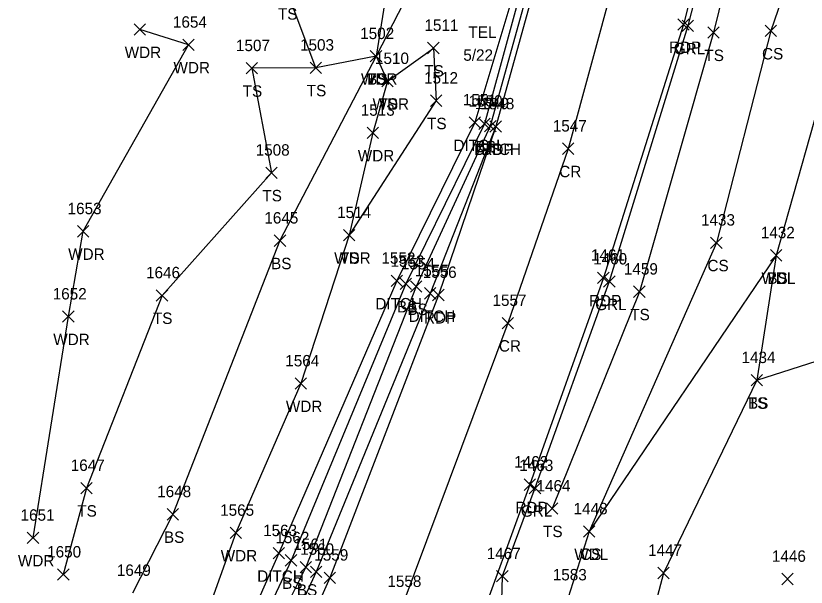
# Model space of a CAD drawing. Extents: x 1551995 to 1555700, y 777276 to 783130.
# Drawn here: x 1554731.9 to 1554870.3, y 777546.8 to 777646.9 of the extents above; entities that cross this region are included whole.
import ezdxf

# ---------------------------------------------------------------- set-up
doc = ezdxf.new("R2010")
doc.units = 0
for name, color, linetype in [('D_A', 7, 'Continuous'), ('D_I', 7, 'Continuous'), ('D_TIC', 7, 'Continuous'), ('DD', 7, 'Continuous'), ('L_A', 7, 'Continuous'), ('L_I', 7, 'Continuous'), ('L_TIC', 7, 'Continuous'), ('LAWA', 7, 'Continuous'), ('LELB', 7, 'Continuous'), ('P_A', 7, 'Continuous'), ('P_I', 7, 'Continuous'), ('P_TIC', 7, 'Continuous'), ('PET', 7, 'Continuous'), ('PRC', 7, 'Continuous'), ('R_A', 7, 'Continuous'), ('R_I', 7, 'Continuous'), ('R_TIC', 7, 'Continuous'), ('RGR', 7, 'Continuous'), ('U_A', 7, 'Continuous'), ('U_C', 7, 'Continuous')]:
    doc.layers.add(name, color=color, linetype=linetype)

msp = doc.modelspace()

# ---------------------------------------------------------------- linework, layer by layer
at = {"layer": 'D_TIC'}
for points in [[(1554811.27, 777627.19), (1554813.27, 777629.19)], [(1554813.27, 777627.19), (1554811.27, 777629.19)], [(1554814.91, 777626.5), (1554816.91, 777628.5)], [(1554816.91, 777626.5), (1554814.91, 777628.5)], [(1554797.58, 777599.46), (1554799.58, 777601.46)], [(1554799.58, 777599.46), (1554797.58, 777601.46)], [(1554803.43, 777597.27), (1554805.43, 777599.27)], [(1554805.43, 777597.27), (1554803.43, 777599.27)], [(1554776.91, 777551.75), (1554778.91, 777553.75)], [(1554778.91, 777551.75), (1554776.91, 777553.75)], [(1554783.48, 777548.49), (1554785.48, 777550.49)], [(1554785.48, 777548.49), (1554783.48, 777550.49)]]:
    msp.add_lwpolyline(points, dxfattribs=at)
at = {"layer": 'DD'}
for points in [[(1554853.39, 777826.98), (1554841.81, 777777.5), (1554835.76, 777743.69), (1554828.13, 777697.14), (1554822.33, 777678.76), (1554820.5, 777673.08), (1554821.28, 777667.69), (1554820.54, 777665.87), (1554819.99, 777658.61), (1554821.52, 777659.17), (1554812.27, 777628.19), (1554798.58, 777600.46), (1554777.91, 777552.75), (1554765.73, 777525.09), (1554749.72, 777489.17), (1554733.83, 777456.87), (1554735, 777456.04), (1554736.9, 777455.11), (1554739.85, 777453.59)], [(1554815.91, 777627.5), (1554804.43, 777598.27), (1554784.48, 777549.49), (1554771.86, 777522.02), (1554755.84, 777486.17), (1554739.85, 777453.59)]]:
    msp.add_lwpolyline(points, dxfattribs=at)
at = {"layer": 'L_TIC'}
for points in [[(1554752.57, 777643.48), (1554754.57, 777645.48)], [(1554754.57, 777643.48), (1554752.57, 777645.48)], [(1554853.06, 777642.96), (1554855.06, 777644.96)], [(1554855.06, 777642.96), (1554853.06, 777644.96)], [(1554863.12, 777643.24), (1554865.12, 777645.24)], [(1554865.12, 777643.24), (1554863.12, 777645.24)], [(1554761.12, 777640.8), (1554763.12, 777642.8)], [(1554763.12, 777640.8), (1554761.12, 777642.8)], [(1554803.99, 777640.24), (1554805.99, 777642.24)], [(1554805.99, 777640.24), (1554803.99, 777642.24)], [(1554793.95, 777638.81), (1554795.95, 777640.81)], [(1554795.95, 777638.81), (1554793.95, 777640.81)], [(1554793.95, 777638.81), (1554795.95, 777640.81)], [(1554795.95, 777638.81), (1554793.95, 777640.81)], [(1554793.95, 777638.81), (1554795.95, 777640.81)], [(1554795.95, 777638.81), (1554793.95, 777640.81)], [(1554783.41, 777636.79), (1554785.41, 777638.79)], [(1554785.41, 777636.79), (1554783.41, 777638.79)], [(1554783.41, 777636.79), (1554785.41, 777638.79)], [(1554785.41, 777636.79), (1554783.41, 777638.79)], [(1554772.19, 777636.7), (1554774.19, 777638.7)], [(1554774.19, 777636.7), (1554772.19, 777638.7)], [(1554795.98, 777634.44), (1554797.98, 777636.44)], [(1554797.98, 777634.44), (1554795.98, 777636.44)], [(1554795.98, 777634.44), (1554797.98, 777636.44)], [(1554797.98, 777634.44), (1554795.98, 777636.44)], [(1554804.49, 777631.02), (1554806.49, 777633.02)], [(1554806.49, 777631.02), (1554804.49, 777633.02)], [(1554812.94, 777626.98), (1554814.94, 777628.98)], [(1554814.94, 777626.98), (1554812.94, 777628.98)], [(1554813.97, 777626.54), (1554815.97, 777628.54)], [(1554815.97, 777626.54), (1554813.97, 777628.54)], [(1554793.4, 777625.38), (1554795.4, 777627.38)], [(1554795.4, 777625.38), (1554793.4, 777627.38)], [(1554775.64, 777618.39), (1554777.64, 777620.39)], [(1554777.64, 777618.39), (1554775.64, 777620.39)], [(1554742.67, 777608.14), (1554744.67, 777610.14)], [(1554744.67, 777608.14), (1554742.67, 777610.14)], [(1554777.13, 777606.5), (1554779.13, 777608.5)], [(1554779.13, 777606.5), (1554777.13, 777608.5)], [(1554789.25, 777607.46), (1554791.25, 777609.46)], [(1554791.25, 777607.46), (1554789.25, 777609.46)], [(1554789.25, 777607.46), (1554791.25, 777609.46)], [(1554791.25, 777607.46), (1554789.25, 777609.46)], [(1554853.56, 777606.14), (1554855.56, 777608.14)], [(1554855.56, 777606.14), (1554853.56, 777608.14)], [(1554864.05, 777603.93), (1554866.05, 777605.93)], [(1554866.05, 777603.93), (1554864.05, 777605.93)], [(1554864.05, 777603.93), (1554866.05, 777605.93)], [(1554866.05, 777603.93), (1554864.05, 777605.93)], [(1554799.18, 777598.92), (1554801.18, 777600.92)], [(1554801.18, 777598.92), (1554799.18, 777600.92)], [(1554800.99, 777598.47), (1554802.99, 777600.47)], [(1554802.99, 777598.47), (1554800.99, 777600.47)], [(1554756.47, 777596.91), (1554758.47, 777598.91)], [(1554758.47, 777596.91), (1554756.47, 777598.91)], [(1554840.07, 777597.56), (1554842.07, 777599.56)], [(1554842.07, 777597.56), (1554840.07, 777599.56)], [(1554740.06, 777593.2), (1554742.06, 777595.2)], [(1554742.06, 777593.2), (1554740.06, 777595.2)], [(1554780.8, 777581.48), (1554782.8, 777583.48)], [(1554782.8, 777581.48), (1554780.8, 777583.48)], [(1554860.66, 777582.06), (1554862.66, 777584.06)], [(1554862.66, 777582.06), (1554860.66, 777584.06)], [(1554860.66, 777582.06), (1554862.66, 777584.06)], [(1554862.66, 777582.06), (1554860.66, 777584.06)], [(1554743.22, 777563.17), (1554745.22, 777565.17)], [(1554745.22, 777563.17), (1554743.22, 777565.17)], [(1554824.8, 777559.58), (1554826.8, 777561.58)], [(1554826.8, 777559.58), (1554824.8, 777561.58)], [(1554758.36, 777558.57), (1554760.36, 777560.57)], [(1554760.36, 777558.57), (1554758.36, 777560.57)], [(1554769.39, 777555.32), (1554771.39, 777557.32)], [(1554771.39, 777555.32), (1554769.39, 777557.32)], [(1554831.26, 777555.58), (1554833.26, 777557.58)], [(1554833.26, 777555.58), (1554831.26, 777557.58)], [(1554831.26, 777555.58), (1554833.26, 777557.58)], [(1554833.26, 777555.58), (1554831.26, 777557.58)], [(1554733.87, 777554.45), (1554735.87, 777556.45)], [(1554735.87, 777554.45), (1554733.87, 777556.45)], [(1554779.06, 777550.51), (1554781.06, 777552.51)], [(1554781.06, 777550.51), (1554779.06, 777552.51)], [(1554781.65, 777549.32), (1554783.65, 777551.32)], [(1554783.65, 777549.32), (1554781.65, 777551.32)], [(1554844.3, 777548.29), (1554846.3, 777550.29)], [(1554846.3, 777548.29), (1554844.3, 777550.29)], [(1554739.18, 777548.01), (1554741.18, 777550.01)], [(1554741.18, 777548.01), (1554739.18, 777550.01)], [(1554866.04, 777547.25), (1554868.04, 777549.25)], [(1554868.04, 777547.25), (1554866.04, 777549.25)]]:
    msp.add_lwpolyline(points, dxfattribs=at)
at = {"layer": 'LAWA'}
for points in [[(1554924.17, 777845.95), (1554911.99, 777797.39), (1554901.73, 777752.36), (1554891.43, 777715.92), (1554886.53, 777681.63), (1554885.54, 777676.35), (1554886.43, 777672.72), (1554885.1, 777668.28), (1554876.24, 777640.92), (1554874.65, 777639.02), (1554865.05, 777604.93), (1554832.26, 777556.58), (1554828.6, 777545), (1554825.77, 777534.55), (1554825.26, 777531.03), (1554824.11, 777527.47), (1554817.13, 777514.36), (1554810.78, 777500.84), (1554797.7, 777469.38), (1554813.54, 777462.7)], [(1554848.67, 777827.4), (1554836.72, 777779.63), (1554829.79, 777744.11), (1554825.78, 777741.3), (1554822.18, 777720.94), (1554819.26, 777705.66), (1554810.77, 777674.16), (1554804.68, 777658.7), (1554794.95, 777639.81), (1554796.98, 777635.44), (1554794.4, 777626.38), (1554790.25, 777608.46), (1554781.8, 777582.48), (1554770.39, 777556.32), (1554759.95, 777527.2), (1554742.53, 777489.58), (1554728.19, 777462.54)], [(1554734.87, 777555.45), (1554741.06, 777594.2), (1554743.67, 777609.14), (1554762.12, 777641.8), (1554753.57, 777644.48)]]:
    msp.add_lwpolyline(points, dxfattribs=at)
at = {"layer": 'LELB'}
for points in [[(1554956.78, 778082.85), (1554952.54, 778067.25), (1554941.7, 778025.45), (1554932.23, 777987.42), (1554924.92, 777953.42), (1554914.28, 777909.64), (1554906.04, 777867.54), (1554895.88, 777821.34), (1554882.23, 777767.05), (1554874.85, 777730.37), (1554865.16, 777689.06), (1554854.06, 777643.96), (1554841.07, 777598.56), (1554825.8, 777560.58)], [(1554954.84, 778026.93), (1554940.94, 777981.64), (1554932.87, 777954.14), (1554929.76, 777924.84), (1554918.75, 777893.91), (1554912.39, 777848.48), (1554900.26, 777799.7), (1554891.71, 777757.62), (1554881.43, 777720.27), (1554874.58, 777680.06), (1554873.83, 777672.65), (1554864.12, 777644.24), (1554854.56, 777607.14), (1554832.26, 777556.58)], [(1554818.74, 777989.99), (1554826.95, 777965.67), (1554828.21, 777938.79), (1554827.61, 777892.43), (1554825.56, 777859.47), (1554820.31, 777829.58), (1554817.04, 777800.55), (1554813.37, 777784.98), (1554810.59, 777751.68), (1554805.09, 777735), (1554803.57, 777724.87), (1554801.62, 777701.82), (1554799.08, 777679.52), (1554798, 777658.89), (1554794.95, 777639.81), (1554778.13, 777607.5), (1554759.36, 777559.57), (1554752.31, 777545.79)], [(1554855.73, 777827.33), (1554843.83, 777776.52), (1554838.11, 777743.68), (1554829.99, 777696.83), (1554823.99, 777679.3), (1554821.48, 777673.86), (1554821.86, 777673.52), (1554823.73, 777663.64), (1554822.4, 777659.03), (1554813.94, 777627.98), (1554800.18, 777599.92), (1554780.06, 777551.51), (1554767.45, 777524.55), (1554751.73, 777488.16), (1554735, 777456.04)], [(1554857.76, 777827.38), (1554846.36, 777775.83), (1554840.77, 777743.18), (1554831.41, 777696.67), (1554825.48, 777677.69), (1554824.51, 777673.63), (1554823.78, 777673.32), (1554824.92, 777663.42), (1554823.59, 777658.72), (1554814.97, 777627.54), (1554801.99, 777599.47), (1554782.65, 777550.32), (1554769.22, 777523.47), (1554754.18, 777487.46), (1554736.9, 777455.11)], [(1554784.41, 777637.79), (1554779.36, 777651.21), (1554780.53, 777680.7), (1554785.91, 777706.67), (1554782.17, 777718.85)], [(1554796.98, 777635.44), (1554804.99, 777641.24), (1554805.49, 777632.02), (1554790.25, 777608.46)], [(1554794.95, 777639.81), (1554784.41, 777637.79), (1554773.19, 777637.7), (1554776.64, 777619.39), (1554757.47, 777597.91), (1554744.22, 777564.17), (1554740.18, 777549.01)], [(1554861.66, 777583.06), (1554884.24, 777590.3), (1554889.44, 777611.11), (1554915.79, 777577.44)], [(1554865.05, 777604.93), (1554861.66, 777583.06), (1554845.3, 777549.29), (1554838.79, 777524.5), (1554825.26, 777531.03), (1554821.87, 777528.28), (1554813.37, 777517.61), (1554805.18, 777504.08), (1554790.4, 777473.73), (1554768.81, 777436.17)]]:
    msp.add_lwpolyline(points, dxfattribs=at)
at = {"layer": 'P_TIC'}
for points in [[(1554847.79, 777644.37), (1554849.79, 777646.37)], [(1554849.79, 777644.37), (1554847.79, 777646.37)], [(1554814.91, 777626.5), (1554816.91, 777628.5)], [(1554816.91, 777626.5), (1554814.91, 777628.5)], [(1554827.61, 777622.61), (1554829.61, 777624.61)], [(1554829.61, 777622.61), (1554827.61, 777624.61)], [(1554833.77, 777599.99), (1554835.77, 777601.99)], [(1554835.77, 777599.99), (1554833.77, 777601.99)], [(1554804.87, 777596.98), (1554806.87, 777598.98)], [(1554806.87, 777596.98), (1554804.87, 777598.98)], [(1554817.04, 777592.07), (1554819.04, 777594.07)], [(1554819.04, 777592.07), (1554817.04, 777594.07)], [(1554820.88, 777563.77), (1554822.88, 777565.77)], [(1554822.88, 777563.77), (1554820.88, 777565.77)], [(1554785.84, 777547.46), (1554787.84, 777549.46)], [(1554787.84, 777547.46), (1554785.84, 777549.46)]]:
    msp.add_lwpolyline(points, dxfattribs=at)
at = {"layer": 'PET'}
for points in [[(1554862.74, 777826.66), (1554851.19, 777774.32), (1554844.64, 777742.45), (1554834.58, 777696.01), (1554825.9, 777662.94), (1554824.47, 777658.25), (1554815.91, 777627.5), (1554805.87, 777597.98), (1554786.84, 777548.46), (1554774.55, 777520.74), (1554758.12, 777485.1), (1554742.1, 777452.42), (1554722.77, 777413.11), (1554709.98, 777388.33), (1554692.97, 777354.45), (1554662.63, 777294.3)], [(1554889.9, 777822.39), (1554877.4, 777767.74), (1554869.61, 777731.46), (1554860.02, 777689.61), (1554848.79, 777645.37), (1554834.77, 777600.99), (1554821.88, 777564.77), (1554812, 777537.71), (1554799.6, 777509.17), (1554784.62, 777476.27), (1554767.28, 777440.72), (1554755.97, 777417.1), (1554737.76, 777381.53), (1554717.46, 777342.52), (1554685.83, 777281.18)]]:
    msp.add_lwpolyline(points, dxfattribs=at)
at = {"layer": 'PRC'}
msp.add_lwpolyline([(1554876.72, 777824.26), (1554864.6, 777770.35), (1554858.03, 777739.92), (1554847.21, 777693.38), (1554836.59, 777653.01), (1554828.61, 777623.61), (1554818.04, 777593.07), (1554799.63, 777543.85), (1554787.19, 777515.25), (1554771.79, 777480.71), (1554754.78, 777446.13), (1554727.16, 777390.73), (1554704.95, 777347.63), (1554675, 777287.76)], dxfattribs=at)
at = {"layer": 'R_TIC'}
for points in [[(1554848.55, 777644.14), (1554850.55, 777646.14)], [(1554850.55, 777644.14), (1554848.55, 777646.14)], [(1554834.81, 777599.33), (1554836.81, 777601.33)], [(1554836.81, 777599.33), (1554834.81, 777601.33)], [(1554821.79, 777563.15), (1554823.79, 777565.15)], [(1554823.79, 777563.15), (1554821.79, 777565.15)], [(1554816.07, 777547.72), (1554818.07, 777549.72)], [(1554818.07, 777547.72), (1554816.07, 777549.72)]]:
    msp.add_lwpolyline(points, dxfattribs=at)
at = {"layer": 'RGR'}
msp.add_lwpolyline([(1555039.56, 778268.3), (1555013.62, 778223), (1554996.63, 778189.88), (1554979.88, 778154.08), (1554968.24, 778124.65), (1554958.2, 778096.32), (1554950.97, 778072.94), (1554937.27, 778027.95), (1554927.65, 777988.1), (1554919.66, 777954.37), (1554909.72, 777910.11), (1554900.5, 777868.18), (1554890.69, 777822.54), (1554878.36, 777767.59), (1554870.52, 777731.32), (1554860.9, 777689.38), (1554849.55, 777645.14), (1554835.81, 777600.33), (1554822.79, 777564.15), (1554817.07, 777548.72), (1554816.7, 777536.06)], dxfattribs=at)

# ---------------------------------------------------------------- texts
at = {"layer": 'D_A'}
for p in [(1554808.51, 777623.19), (1554812.15, 777622.5), (1554794.82, 777595.46), (1554800.66, 777593.27), (1554774.14, 777547.75)]:
    msp.add_text('DITCH', height=2, dxfattribs=at).set_placement(p)
at = {"layer": 'D_I'}
for s, p in [('1551', (1554810.15, 777631.19)), ('1548', (1554813.22, 777630.5)), ('1552', (1554795.89, 777603.46)), ('1555', (1554801.74, 777601.27)), ('1563', (1554775.17, 777555.75)), ('1560', (1554781.66, 777552.49))]:
    msp.add_text(s, height=2, dxfattribs=at).set_placement(p)
at = {"layer": 'L_A'}
for s, p in [('TS', (1554777.77, 777646.21)), ('WDR', (1554750.93, 777639.48)), ('TS', (1554852.47, 777638.96)), ('CS', (1554862.56, 777639.24)), ('WDR', (1554759.48, 777636.8)), ('TS', (1554803.4, 777636.24)), ('WDR', (1554792.32, 777634.81)), ('TS', (1554793.36, 777634.81)), ('BS', (1554793.4, 777634.81)), ('TS', (1554771.6, 777632.7)), ('TS', (1554782.82, 777632.79)), ('TS', (1554782.82, 777632.79)), ('WDR', (1554794.34, 777630.44)), ('TS', (1554795.39, 777630.44)), ('TS', (1554803.89, 777627.02)), ('BS', (1554812.38, 777622.98)), ('BS', (1554813.41, 777622.54)), ('WDR', (1554791.76, 777621.38)), ('TS', (1554775.05, 777614.39)), ('WDR', (1554741.03, 777604.14)), ('BS', (1554776.57, 777602.5)), ('WDR', (1554787.62, 777603.46)), ('TS', (1554788.66, 777603.46)), ('CS', (1554853, 777602.14)), ('WDL', (1554862.46, 777599.93)), ('BS', (1554863.49, 777599.93)), ('BS', (1554798.62, 777594.92)), ('BS', (1554800.43, 777594.47)), ('TS', (1554755.87, 777592.91)), ('TS', (1554839.48, 777593.56)), ('WDR', (1554738.42, 777589.2)), ('WDR', (1554779.16, 777577.48)), ('TS', (1554860.07, 777578.06)), ('BS', (1554860.1, 777578.06)), ('TS', (1554742.63, 777559.17)), ('TS', (1554824.21, 777555.58)), ('BS', (1554757.8, 777554.57)), ('WDR', (1554767.75, 777551.32)), ('WDL', (1554829.67, 777551.58)), ('CS', (1554830.7, 777551.58)), ('WDR', (1554732.23, 777550.45)), ('BS', (1554778.5, 777546.51)), ('BS', (1554781.09, 777545.32))]:
    msp.add_text(s, height=2, dxfattribs=at).set_placement(p)
at = {"layer": 'L_I'}
for s, p in [('1654', (1554759.38, 777644.8)), ('1511', (1554803.43, 777644.24)), ('1502', (1554792.18, 777642.81)), ('1502', (1554792.18, 777642.81)), ('1502', (1554792.18, 777642.81)), ('1507', (1554770.42, 777640.7)), ('1503', (1554781.64, 777640.79)), ('1503', (1554781.64, 777640.79)), ('1510', (1554794.77, 777638.44)), ('1510', (1554794.77, 777638.44)), ('1512', (1554803.36, 777635.02)), ('1550', (1554811.16, 777630.98)), ('1549', (1554812.27, 777630.54)), ('1513', (1554792.27, 777629.38)), ('1508', (1554773.87, 777622.39)), ('1653', (1554740.93, 777612.14)), ('1645', (1554775.39, 777610.5)), ('1514', (1554788.13, 777611.46)), ('1514', (1554788.13, 777611.46)), ('1433', (1554851.87, 777610.14)), ('1432', (1554862.35, 777607.93)), ('1432', (1554862.35, 777607.93)), ('1553', (1554797.48, 777602.92)), ('1554', (1554799.3, 777602.47)), ('1646', (1554754.67, 777600.91)), ('1459', (1554838.37, 777601.56)), ('1652', (1554738.32, 777597.2)), ('1434', (1554858.96, 777586.06)), ('1434', (1554858.96, 777586.06)), ('1564', (1554779.06, 777585.48)), ('1647', (1554741.48, 777567.17)), ('1464', (1554823.06, 777563.58)), ('1648', (1554756.62, 777562.57)), ('1565', (1554767.65, 777559.32)), ('1448', (1554829.56, 777559.58)), ('1448', (1554829.56, 777559.58)), ('1651', (1554732.69, 777558.45)), ('1562', (1554777.32, 777554.51)), ('1561', (1554780.48, 777553.32)), ('1650', (1554737.35, 777552.01)), ('1447', (1554842.6, 777552.29)), ('1446', (1554864.29, 777551.25)), ('1649', (1554749.56, 777548.79)), ('1583', (1554825.91, 777548))]:
    msp.add_text(s, height=2, dxfattribs=at).set_placement(p)
at = {"layer": 'P_A'}
for s, p in [('RDP', (1554846.28, 777640.37)), ('RDP', (1554813.4, 777622.5)), ('CR', (1554827.04, 777618.61)), ('RDP', (1554832.26, 777595.99)), ('RDP', (1554803.35, 777592.98)), ('CR', (1554816.47, 777588.07)), ('RDP', (1554819.37, 777559.77))]:
    msp.add_text(s, height=2, dxfattribs=at).set_placement(p)
at = {"layer": 'P_I'}
for s, p in [('1548', (1554813.22, 777630.5)), ('1547', (1554825.91, 777626.61)), ('1461', (1554832.6, 777603.99)), ('1556', (1554803.12, 777600.98)), ('1557', (1554815.35, 777596.07)), ('1462', (1554819.14, 777567.77)), ('1559', (1554784.14, 777551.46)), ('1558', (1554796.94, 777546.85))]:
    msp.add_text(s, height=2, dxfattribs=at).set_placement(p)
at = {"layer": 'R_A'}
for p in [(1554847.1, 777640.14), (1554833.35, 777595.33), (1554820.33, 777559.15)]:
    msp.add_text('GRL', height=2, dxfattribs=at).set_placement(p)
at = {"layer": 'R_I'}
for s, p in [('1460', (1554832.98, 777603.33)), ('1463', (1554820.05, 777567.15)), ('1467', (1554814.33, 777551.72))]:
    msp.add_text(s, height=2, dxfattribs=at).set_placement(p)
at = {"layer": 'U_A'}
msp.add_text('TEL', height=2, dxfattribs=at).set_placement((1554811.14, 777643.01))
at = {"layer": 'U_C'}
msp.add_text('5/22', height=2, dxfattribs=at).set_placement((1554810.24, 777639.01))

doc.saveas('drawing.dxf')
